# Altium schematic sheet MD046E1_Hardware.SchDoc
size 431 x 279 mm; Date: Not shown in title block; ApprovedBy: Not shown in title block; CheckedBy: Not shown in title block; Author: Not shown in title block; CompanyName: Not shown in title block; Engineer: Not shown in title block; Organization: Not shown in title block; Address1: Not shown in title block; Address2: Not shown in title block; Address3: Not shown in title block; Address4: Not shown in title block; DocumentNumber: 3; Revision: Use project parameter SCH_Rev; SheetNumber: 3; SheetTotal: 3; PageSetup: Record=PageOptions¦CenterHorizontal=True¦CenterVertical=True¦PrintScale=1.00¦XCorrection=1.00¦YCorrection=1.00¦PrintKind=0¦BorderSize=5000000¦LeftOffset=0¦BottomOffset=0¦Orientation=2¦PaperLength=1000¦PaperWidth=1000¦Scale=100¦PaperSource=15¦PrintQuality=600¦MediaType=1¦DitherType=10¦PaperKind=Letter¦PrintScaleMode=1
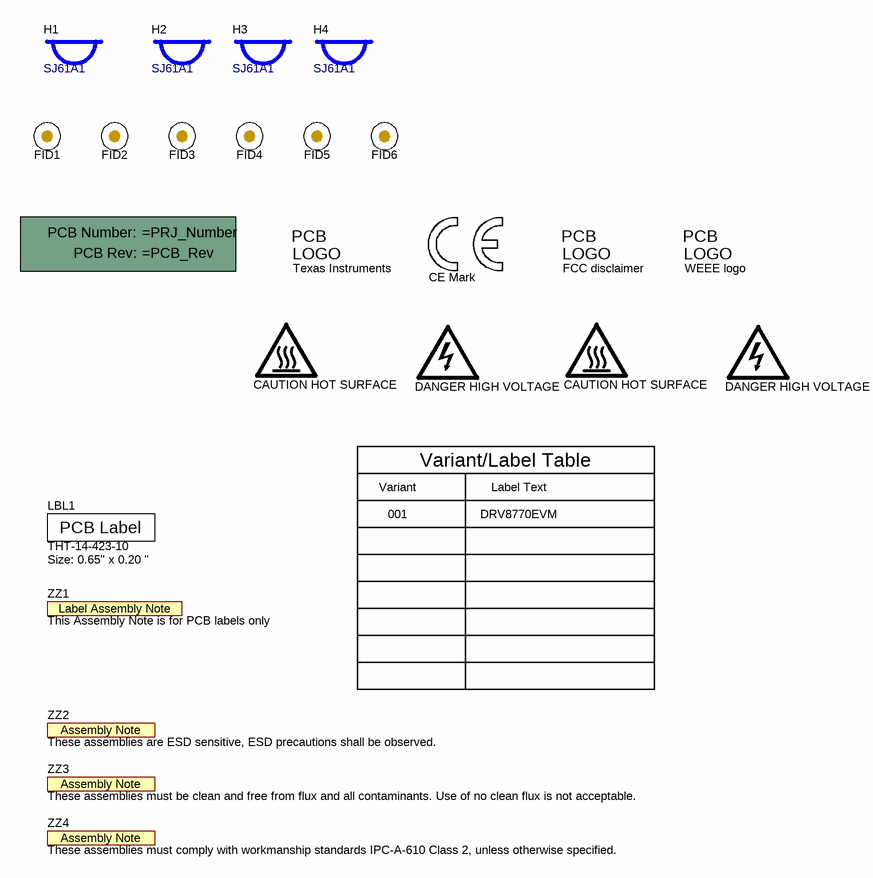
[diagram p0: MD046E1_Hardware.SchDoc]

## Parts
!PCB1  Printed Circuit Board  (value not drawn)  (mechanical)
FID1  Fiducial  [Fiducial10-20]  (value not drawn)
FID2  Fiducial  [Fiducial10-20]  (value not drawn)
FID3  Fiducial  [Fiducial10-20]  (value not drawn)
FID4  Fiducial  [Fiducial10-20]  (value not drawn)
FID5  Fiducial  [Fiducial10-20]  (value not drawn)
FID6  Fiducial  [Fiducial10-20]  (value not drawn)
H1  SJ61A1  [Bumpon_SJ61A1]
H2  SJ61A1  [Bumpon_SJ61A1]
H3  SJ61A1  [Bumpon_SJ61A1]
H4  SJ61A1  [Bumpon_SJ61A1]
LBL1  THT-14-423-10  Note: Size: 0.65" x 0.20 "  [Label_650x200]
Logo1  CE Mark  [CE_Mark_5mm]  (no BOM)
Logo2  Texas Instruments  [TI_Stacked_Overlay_Small]  (no BOM)
Logo3  FCC disclaimer  [FCC_disclaimer]  (no BOM)
Logo4  WEEE logo  [WEEE_Minimum]  (no BOM)
LOGO5  CAUTION HOT SURFACE  [IEC_HotSurface_Small]  (no BOM)
LOGO6  CAUTION HOT SURFACE  [IEC_HotSurface_Small]  (no BOM)
LOGO7  DANGER HIGH VOLTAGE  [IEC_HighVoltage_Small]  (no BOM)
LOGO8  DANGER HIGH VOLTAGE  [IEC_HighVoltage_Small]  (no BOM)
ZZ1  This Assembly Note is for PCB labels only  [AssemblyNoteLabel]  (no BOM)
ZZ2  These assemblies are ESD sensitive, ESD precautions shall be observed.  [AssemblyNote]  (no BOM)
ZZ3  These assemblies must be clean and free from flux and all contaminants. Use of no clean flux is not acceptable.  [AssemblyNote]  (no BOM)
ZZ4  These assemblies must comply with workmanship standards IPC-A-610 Class 2, unless otherwise specified.  [AssemblyNote]  (no BOM)

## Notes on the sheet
- Variant
- Variant/Label Table
- Label Text
- 001
- DRV8770EVM

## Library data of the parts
!PCB1 = CMP-0003618-2: Manufacturer: Any
FID1-FID6 = CMP-0077181-1: Fiducial mark.  There is nothing to buy or mount.
H1-H4 = CMP-0003621-1: Bumpon, Cylindrical, 0.312 X 0.200, Black; Manufacturer: 3M
LBL1 = CMP-0003625-1: Thermal Transfer Printable Labels, 0.650" W x 0.200" H - 10,000 per roll; Manufacturer: Brady; CompType: Label
Logo1 = CMP-0074844-1: SymbolCreator: a0412235
Logo2 = CMP-0074838-1: Texas Instrument Corporate Signature; SymbolCreator: a0412235; Lib Reference: TI_Logo; Library Reference: Logo
Logo3 = CMP-0074847-1: FCC_disclaimer; Library Reference: Logo
Logo4 = CMP-0074769-1
LOGO5 LOGO6 = CMP-0074837-1: IEC 61010-1 Hot Surface Warning; SymbolCreator: a0412235; Lib Reference: IEC_HotSurface
LOGO7 LOGO8 = CMP-0074835-1: IEC 61010-1 High Voltage Warning; SymbolCreator: a0412235; Lib Reference: IEC_HighVoltage
ZZ1 = CMP-0003616-3
ZZ2 = CMP-0077236-1
ZZ3 = CMP-0077237-1
ZZ4 = CMP-0077238-1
